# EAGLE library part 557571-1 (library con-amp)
AMP connector
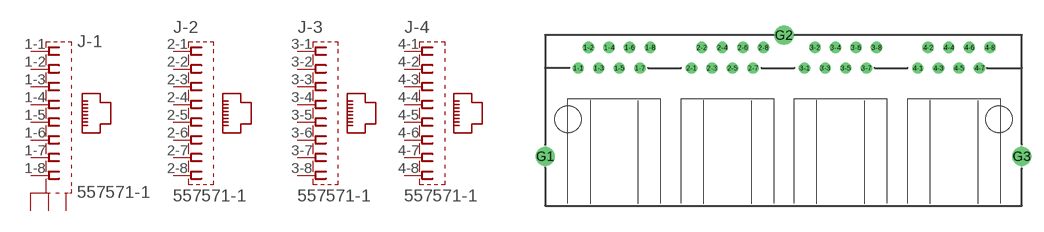
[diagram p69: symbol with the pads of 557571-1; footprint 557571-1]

Designator prefix J; gates -2=JACK8_SH -3=JACK8_SH -4=JACK8_SH -1=JACK8SH3

## 557571-1 (MPN: 5557571-1; OC_FARNELL: unknown; OC_NEWARK: 88M9441)  [557571-1]
1-1  -1:1  pas
1-2  -1:2  pas
1-3  -1:3  pas
1-4  -1:4  pas
1-5  -1:5  pas
1-6  -1:6  pas
1-7  -1:7  pas
1-8  -1:8  pas
2-1  -2:1  pas
2-2  -2:2  pas
2-3  -2:3  pas
2-4  -2:4  pas
2-5  -2:5  pas
2-6  -2:6  pas
2-7  -2:7  pas
2-8  -2:8  pas
3-1  -3:1  pas
3-2  -3:2  pas
3-3  -3:3  pas
3-4  -3:4  pas
3-5  -3:5  pas
3-6  -3:6  pas
3-7  -3:7  pas
3-8  -3:8  pas
4-1  -4:1  pas
4-2  -4:2  pas
4-3  -4:3  pas
4-4  -4:4  pas
4-5  -4:5  pas
4-6  -4:6  pas
4-7  -4:7  pas
4-8  -4:8  pas
G1  -1:9  pas
G2  -1:10  pas
G3  -1:11  pas

## Footprint 557571-1 (pad centres in mm)
Modular Jack Shielded
drill 0.889 round: 1-1 -25.4,6.35; 1-2 -24.13,8.89; 1-3 -22.86,6.35; 1-4 -21.59,8.89; 1-5 -20.32,6.35; 1-6 -19.05,8.89; 1-7 -17.78,6.35; 1-8 -16.51,8.89; 2-1 -11.43,6.35; 2-2 -10.16,8.89; 2-3 -8.89,6.35; 2-4 -7.62,8.89; 2-5 -6.35,6.35; 2-6 -5.08,8.89; 2-7 -3.81,6.35; 2-8 -2.54,8.89; 3-1 2.54,6.35; 3-2 3.81,8.89; 3-3 5.08,6.35; 3-4 6.35,8.89; 3-5 7.62,6.35; 3-6 8.89,8.89; 3-7 10.16,6.35; 3-8 11.43,8.89; 4-1 16.51,6.35; 4-2 17.78,8.89; 4-3 19.05,6.35; 4-4 20.32,8.89; 4-5 21.59,6.35; 4-6 22.86,8.89; 4-7 24.13,6.35; 4-8 25.4,8.89
drill 1.575 pad 2.184 round: G1 -29.464,-4.572; G2 0,10.414; G3 29.337,-4.572
hole 3.251 at -26.67,0
hole 3.251 at 26.543,0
